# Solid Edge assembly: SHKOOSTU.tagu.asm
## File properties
Author: Türk
Template: Iso Assembly.asm
Last saved by: Türk
Revision: 18
Application: Solid Edge
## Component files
Shockabsorber.par
ShKolvikoostu.asm
Shkaan.par
Poldikoostu5.asm
Taguminevedru.par
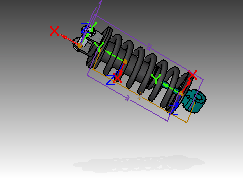
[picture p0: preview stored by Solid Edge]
